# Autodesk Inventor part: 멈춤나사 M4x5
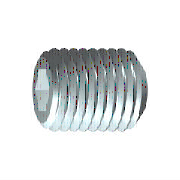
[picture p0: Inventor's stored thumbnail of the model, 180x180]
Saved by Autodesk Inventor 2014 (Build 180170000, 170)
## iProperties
IsCustomPart: 1
Created: 2012-02
Part Number: 멈춤나사 M4x5
Material: 강철, 연강
Description: 6각 소켓 머리 없는 멈춤 나사
Document SubType Name: Modeling
Standard: KS B 1028
Designer: mduedu
Standards Organization: KS
Language: ko-KR
Size Designation: 납작점M4x5
Categories: <MemberInstance><Categories><Category DisplayName="조임쇠" InternalName="e4da775c-781d-43d5-af7c-5136215cf5a6" Mnemonic="FSTN"><Category DisplayName="볼트" InternalN
Density: 1 g/cm^3
Appearance: 강철
Author: mduedu
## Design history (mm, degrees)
sketch "스케치1"
  geometry: L1 (0, 0)-(1.833, 0); L2 (5, 1.155)-(5, 2); L3 (5, 2)-(0, 2); L4 (5, 1.155)-(2.5, 1.155); L5 (2.5, 1.155)-(1.833, 0); L6 (0, -0.4)-(0, 2.4) reference; L7 (0, 2)-(0, 0)
  constraints: 13 end point, 3 parallel, 1 collinear, 1 perpendicular, 1 point on line
  dimensions: "d0" = 2.5 distance of L2.start L4.end (= INTI); "d1" = 60 deg angle of L5 L1; "d2" = 4 diameter of L3 L1 (= NND); "d3" = 2.3094 diameter of L4 L1 (= 1.1547 x SW); "d5" = 5 distance from line of L2 L3.end (= NLG)
revolve "본체" sketch "스케치1" stored, may be unused: angle "d6" = 90 deg
sketch "스케치2"
  geometry: L1 (-0.577, 1)-(0.577, 1); L2 (0.577, 1)-(1.155, 0); L3 (1.155, 0)-(0.577, -1); L4 (0.577, -1)-(-0.577, -1); L5 (-0.577, -1)-(-1.155, 0); L6 (-1.155, 0)-(-0.577, 1); A1 r 1.155 centre (0, 0) between (-0.577, 1) and (0.577, 1) reference; 2 further points
  constraints: 12 end point, 2 point on circle, 1 coincident, 1 horizontal, 11 other
extrude "슬롯" join sketch "스케치2" taper "d9" = 0 deg; stored distance "d21" = 10
workaxis "Work Axis1"
workplane "Work Plane1"
node "작업점1"
  node "작업축2"
body "Solid1"
chamfer "모따기1" distance "d7" = 0.42941 (= -0.5 x GD1 + 0.5 x NND); stored, may be unused: angle "d8" = 45 deg (= FAWI), second distance "d29" = 0.42941 (= -0.5 x GD1 + 0.5 x NND)
feature "스레드" dims "d11" = 5 (= NLG), "d12" = 0
chamfer "모따기2" distance "d13" = 0.42941 (= -0.5 x GD1 + 0.5 x NND); stored, may be unused: angle "d14" = 45 deg (= FAWI), second distance "d30" = 0.42941 (= -0.5 x GD1 + 0.5 x NND)
other parameters: "NND" = 4 [user parameter; used in 5 equation terms], "NLG" = 5 [user parameter; used in 2 equation terms], "INTI" = 2.5 [user parameter; used in 1 equation term], "FAWI" = 45 deg [user parameter; used in 2 equation terms], "SW" = 2 [user parameter; used in 2 equation terms], "GD1" = 3.14117 (= THREADDIA - 1.2269 x PTC) [user parameter; used in 4 equation terms], "d4" = 0, "FAWI1" = 45 deg [user parameter], "d15" = 0, "d31" = 0, "GUL" = 0.42941 (= 0.61345 x PTC) [user parameter], "SPD" = 2.5 [user parameter], "TPU" = 14.28571 (computed from PTC) [user parameter], "TOA" = 30 deg [user parameter], "THREADDIA" = 4 [user parameter; used in 1 equation term], "PTC" = 0.7 [user parameter; used in 4 equation terms], "GAL" = 0.42941 (= 0.61345 x PTC) [user parameter], "E0" = 2.31 (= 1.155 x SW) [user parameter]
